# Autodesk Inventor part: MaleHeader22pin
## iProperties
Shininess: 64.0
Length Units: 11272
Angle Units: 11279
Time Units: 11290
Mass Units: 11286
Length Display Precision: 3
Angle Display Precision: 2
Compacted: True
Part Number: MaleHeader22pin
Document SubType Name: Modeling
Created: 2006-08
Designer: jpalmisano
Manufacturer: Standard
Standards Organization: Custom
Density: 0.0
Volumn: 0.0
Area: 0.0
PropertySet Name: Model Information
Control State: 0
Master: False
Checked Out: False
Author: jpalmisano
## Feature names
1. Extrusion1
2. Extrusion2
3. Extrusion6
